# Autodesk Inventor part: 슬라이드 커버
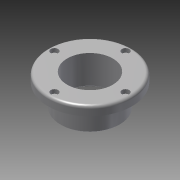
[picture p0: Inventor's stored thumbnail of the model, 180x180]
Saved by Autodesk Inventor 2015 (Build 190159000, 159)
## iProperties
Created: 2015-10
Part Number: 슬라이드 커버
Document SubType Name: Modeling
Designer: mdu
Density: 7.86 g/cm^3
Material: Steel, Mild
Mass: 598.523 g
Surface Area: 229.996 cm^2
Volume: 76.148 cm^3
Appearance: Steel
Author: mdu
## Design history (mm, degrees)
sketch "스케치1"
  geometry: C1 r 46 at (0, -39.25) reference; C2 r 32.5 at (0, -39.25) reference; 1 further point
  node "참조1"
  node "참조2"
extrude "돌출1" new body sketch "스케치1" distance "d0" = 10; taper "d1" = 0 deg
extrude "돌출2" join sketch "스케치1" distance "d2" = 25; taper "d3" = 0 deg
hole "구멍1" diameter "d6" = 50; stored, may be unused: countersink angle "d10" = 90 deg, drill point angle "d12" = 118 deg; dims "d4" = 10, "d5" = 10, "d7" = 6, "d8" = 4, "d9" = 2, "d11" = 8
sketch "스케치2"
  geometry: C1 r 46 at (0, 0) reference; C2 r 1.621 at (0, 39) reference; C3 r 1.621 at (39, 0) reference; C4 r 1.621 at (0, -39) reference; C5 r 1.621 at (-39, 0) reference; C6 r 33.5 at (0, 0) reference; 1 further point
hole "구멍2" sketch "스케치2" at (0, 39) diameter "d13" = 4.5; stored, may be unused: countersink angle "d17" = 90 deg, drill point angle "d19" = 118 deg; dims "d14" = 6, "d15" = 8, "d16" = 4.4, "d18" = 8
fillet "모깎기1" dims "d23" = 3
chamfer "모따기1" distance "d24" = 1; stored, may be unused: second distance "d25" = 2, angle "d26" = 45 deg
sketch "스케치3"
  geometry: C1 r 25 at (0, 0); C2 r 30 at (0, 0); C3 r 26 at (0, 0) reference; 1 further point
  constraints: 2 centre point, 2 coincident
  dimensions: "d27" = 60 diameter of C2
extrude "돌출3" cut sketch "스케치3" distance "d28" = 3; taper "d29" = 0 deg
chamfer "모따기2" distance "d30" = 1; stored, may be unused: second distance "d31" = 2, angle "d32" = 45 deg
node "솔리드1"
pattern_circular "원형 패턴1" dims angle "d21" = 360 deg
node "참조3"
